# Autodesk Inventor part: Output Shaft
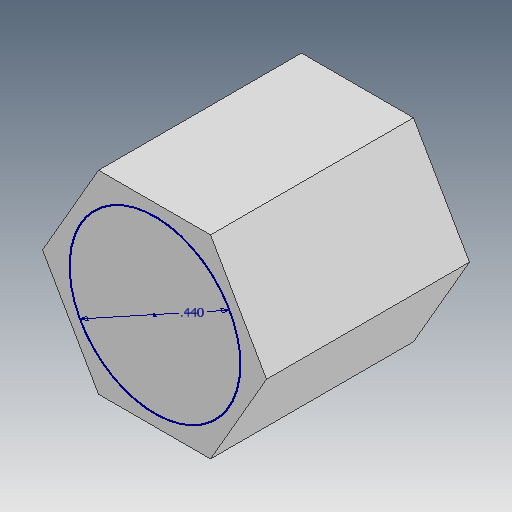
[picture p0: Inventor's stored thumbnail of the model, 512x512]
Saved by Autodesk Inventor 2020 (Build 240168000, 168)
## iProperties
Created: 2021-01
Part Number: Output Shaft
Material: Generic
Document SubType Name: Modeling
Designer: Greg
Density: 1 g/cm^3
Appearance: Default
Author: Greg
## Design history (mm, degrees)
sketch "Sketch1"
  geometry: L1 (7.332, 0)-(3.666, -6.35); L2 (3.666, -6.35)-(-3.666, -6.35); L3 (-3.666, -6.35)-(-7.332, 0); L4 (-7.332, 0)-(-3.666, 6.35); L5 (-3.666, 6.35)-(3.666, 6.35); L6 (3.666, 6.35)-(7.332, 0); 2 further points
  constraints: 12 end point, 1 coincident, 13 other
  dimensions: "d0" = 12.7 distance between parallel lines of L2 L5
extrude "Extrusion1" new body sketch "Sketch1" distance "d1" = 13.2842; taper "d2" = 0 deg
sketch "Sketch3"
  geometry: C1 r 5.588 at (0, 0); 1 further point
  constraints: 1 centre point, 1 coincident
  dimensions: "d3" = 11.176 diameter of C1
body "Solid1"
